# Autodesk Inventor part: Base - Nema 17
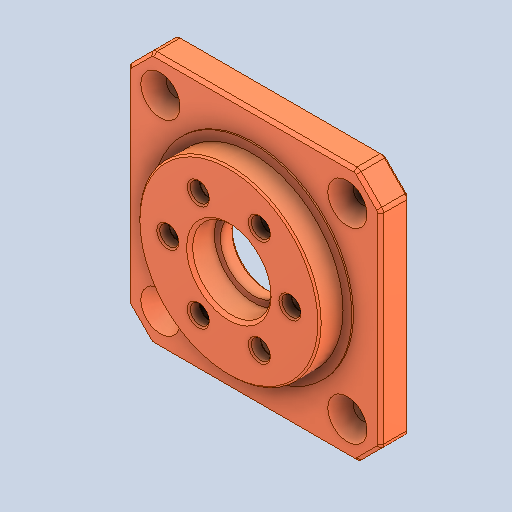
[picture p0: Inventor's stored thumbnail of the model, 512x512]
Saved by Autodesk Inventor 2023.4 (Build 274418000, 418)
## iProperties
Created: 2025-06
Part Number: Base - Nema 17
Material: Steel
Document SubType Name: Modeling
Designer: mel
Density: 7.85 g/cm^3
Appearance: Par défaut
Author: mel
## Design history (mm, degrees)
feature "Base - Nema 17"
node "Solide1"
